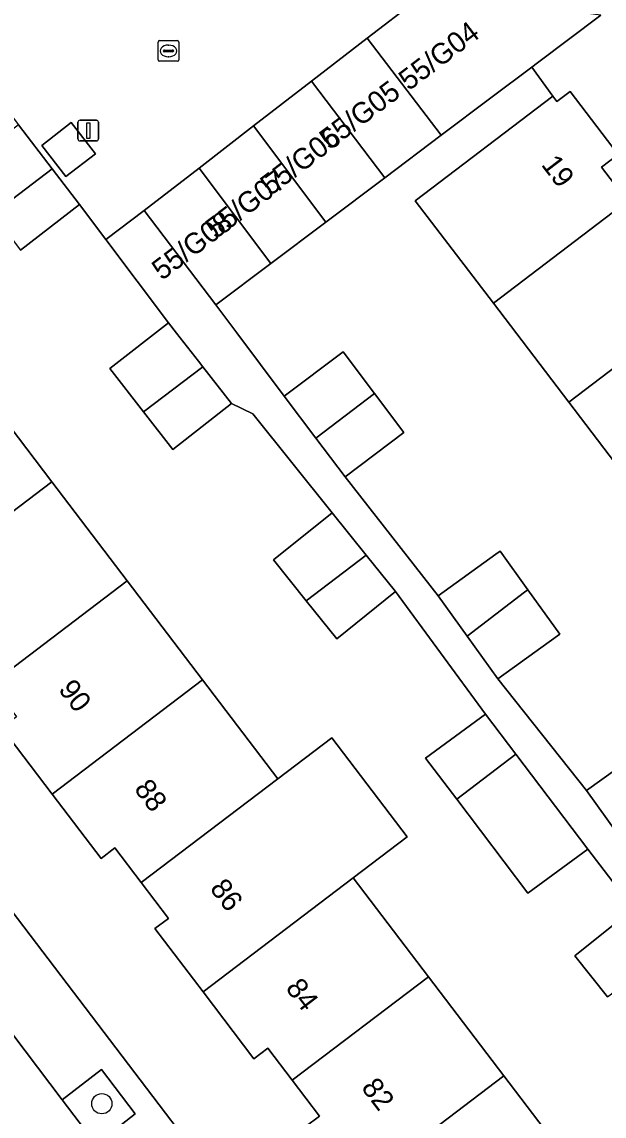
# Model space of a CAD drawing. Extents: x 160030 to 160839, y 385325 to 386450.
# Drawn here: x 160374.7 to 160402.8, y 385654.3 to 385707.1 of the extents above; entities that cross this region are included whole.
import ezdxf

# ---------------------------------------------------------------- set-up
doc = ezdxf.new("R2010")
doc.units = 0
for name, color, linetype in [('IMGEO_Berm_groen', 7, 'Continuous'), ('IMGEO_Boom', 7, 'Continuous'), ('IMGEO_Erf', 7, 'Continuous'), ('IMGEO_Fietspad_gesloten', 7, 'Continuous'), ('IMGEO_Kolk', 7, 'Continuous'), ('IMGEO_Lichtmast', 7, 'Continuous'), ('IMGEO_Muur', 7, 'Continuous'), ('IMGEO_Pand', 7, 'Continuous'), ('IMGEO_Pand_nummerreeks', 7, 'Continuous'), ('IMGEO_Voetpad_open', 7, 'Continuous')]:
    doc.layers.add(name, color=color, linetype=linetype)

msp = doc.modelspace()

# ---------------------------------------------------------------- linework, layer by layer
at = {"layer": 'IMGEO_Berm_groen'}
msp.add_lwpolyline([(160378.552, 385656.522), (160376.655, 385655.061), (160378.29, 385652.906), (160380.176, 385654.395)], close=True, dxfattribs=at)
at = {"layer": 'IMGEO_Boom'}
msp.add_circle((160378.564, 385654.88), 0.489, dxfattribs=at)
at = {"layer": 'IMGEO_Erf'}
for points in [[(160339.544, 385709.767), (160401.163, 385628.731)], [(160402.624, 385707.372), (160399.573, 385705.078), (160399.299, 385704.872), (160400.308, 385703.476), (160400.507, 385703.214), (160401.15, 385703.703), (160403.466, 385700.66), (160402.665, 385700.05), (160403.917, 385698.405)], [(160404.717, 385683.933), (160401.083, 385688.708), (160397.448, 385693.481), (160393.681, 385698.43), (160400.308, 385703.476), (160399.299, 385704.872), (160397.319, 385703.383), (160394.926, 385701.583), (160392.208, 385699.539), (160389.361, 385697.398), (160386.709, 385695.404), (160384.056, 385693.409), (160385.069, 385692.057), (160387.362, 385688.996), (160390.2, 385691.139), (160391.722, 385689.123), (160393.136, 385687.25), (160390.298, 385685.107), (160394.781, 385679.375), (160397.569, 385681.378), (160397.77, 385681.523), (160399.107, 385679.662), (160400.647, 385677.518), (160400.541, 385677.442), (160397.657, 385675.37), (160401.938, 385669.984), (160404.776, 385672.024)], [(160402.952, 385660.033), (160401.368, 385662.005), (160404.205, 385664.283), (160402.007, 385667.157), (160399.117, 385665.04), (160395.68, 385669.572), (160394.181, 385671.549), (160397.071, 385673.666), (160392.729, 385679.578), (160389.892, 385677.3), (160388.42, 385679.133), (160386.836, 385681.105), (160389.673, 385683.383), (160385.841, 385688.154), (160384.817, 385688.644), (160381.985, 385686.435), (160380.575, 385688.242), (160378.948, 385690.329), (160381.78, 385692.538), (160378.755, 385696.565), (160377.494, 385698.243), (160374.645, 385696.051)], [(160372.518, 385689.652), (160376.151, 385684.877), (160379.784, 385680.102), (160383.417, 385675.327), (160387.05, 385670.552), (160389.651, 385672.531), (160393.284, 385667.756), (160390.683, 385665.777), (160394.316, 385661.002), (160397.949, 385656.227), (160401.582, 385651.452)], [(160388.374, 385653.761), (160389.06, 385654.283), (160387.75, 385656.007), (160386.576, 385657.553), (160385.902, 385657.041), (160383.447, 385660.272), (160381.127, 385663.326), (160381.777, 385663.819), (160380.467, 385665.544), (160379.199, 385667.213), (160378.527, 385666.703), (160376.166, 385669.811), (160373.74, 385673.004)]]:
    msp.add_lwpolyline(points, dxfattribs=at)
at = {"layer": 'IMGEO_Fietspad_gesloten'}
msp.add_lwpolyline([(160397.145, 385622.614), (160400.065, 385624.282), (160397.346, 385627.892), (160393.079, 385633.494), (160391.247, 385635.898), (160385.777, 385643.076), (160383.977, 385645.439), (160378.29, 385652.906), (160376.655, 385655.061), (160371.275, 385662.152), (160369.368, 385664.665), (160363.85, 385671.938), (160361.976, 385674.409), (160356.639, 385681.442), (160354.764, 385683.91), (160349.583, 385690.729), (160347.708, 385693.198), (160342.44, 385700.132), (160340.557, 385702.595), (160336.836, 385707.457)], dxfattribs=at)
at = {"layer": 'IMGEO_Kolk'}
for p, q in [((160381.277, 385705.226), (160381.277, 385706.078)), ((160381.352, 385706.152), (160382.204, 385706.152)), ((160381.765, 385705.932), (160381.79, 385705.932)), ((160382.278, 385706.078), (160382.278, 385705.226)), ((160381.536, 385705.646), (160381.536, 385705.658)), ((160381.974, 385705.609), (160381.576, 385705.609)), ((160381.579, 385705.695), (160381.977, 385705.695)), ((160381.788, 385705.372), (160381.763, 385705.372)), ((160382.02, 385705.658), (160382.02, 385705.646)), ((160382.204, 385705.152), (160381.352, 385705.152))]:
    msp.add_line(p, q, dxfattribs=at)
for points in [[(160381.277, 385705.226), (160381.277, 385706.078)], [(160381.352, 385706.152), (160382.204, 385706.152)], [(160382.278, 385706.078), (160382.278, 385705.226)], [(160382.204, 385705.152), (160381.352, 385705.152)]]:
    msp.add_lwpolyline(points, dxfattribs=at)
for centre, radius, start, end in [((160381.354, 385706.076), 0.0765, 91.552, 178.448), ((160381.354, 385706.076), 0.0765, 91.552, 178.448), ((160382.202, 385706.076), 0.0765, 1.552, 88.448), ((160382.202, 385706.076), 0.0765, 1.552, 88.448), ((160381.576, 385705.655), 0.0403, 85.8775, 175.7526), ((160381.573, 385705.645), 0.0366, 178.938, 274.7102), ((160381.977, 385705.652), 0.043, 264.8664, 352.4533), ((160381.981, 385705.657), 0.0386, 1.7309, 96.639), ((160381.354, 385705.228), 0.0765, 181.552, 268.448), ((160381.354, 385705.228), 0.0765, 181.552, 268.448), ((160382.202, 385705.228), 0.0765, 271.552, 358.448), ((160382.202, 385705.228), 0.0765, 271.552, 358.448)]:
    msp.add_arc(centre, radius, start, end, dxfattribs=at)
for centre, major_axis, ratio, start_param, end_param in [((160381.764, 385705.652), (-0.387, 0.002), 0.722429, 4.712389, 7.853982), ((160381.789, 385705.652), (-0.39, 0.002), 0.717154, 1.570796, 4.712389)]:
    msp.add_ellipse(centre, major_axis=major_axis, ratio=ratio, start_param=start_param, end_param=end_param, dxfattribs=at)
at = {"layer": 'IMGEO_Lichtmast'}
for p, q in [((160377.413, 385701.41), (160377.413, 385702.21)), ((160377.413, 385702.21), (160377.413, 385701.41)), ((160377.513, 385702.31), (160378.303, 385702.31)), ((160378.303, 385702.31), (160377.513, 385702.31)), ((160378.403, 385702.21), (160378.403, 385701.41)), ((160378.403, 385701.41), (160378.403, 385702.21)), ((160378.303, 385701.31), (160377.513, 385701.31)), ((160377.513, 385701.31), (160378.303, 385701.31))]:
    msp.add_line(p, q, dxfattribs=at)
msp.add_lwpolyline([(160377.833, 385702.185), (160377.983, 385702.185), (160377.983, 385701.435), (160377.833, 385701.435), (160377.833, 385702.185)], dxfattribs=at)
for centre, start, end in [((160377.513, 385702.21), 90, 180), ((160377.513, 385702.21), 90, 180), ((160378.303, 385702.21), 0, 90), ((160378.303, 385702.21), 360, 90), ((160377.513, 385701.41), 180, 270), ((160377.513, 385701.41), 180, 270), ((160378.303, 385701.41), 270, 0), ((160378.303, 385701.41), 270, 0)]:
    msp.add_arc(centre, 0.1, start, end, dxfattribs=at)
at = {"layer": 'IMGEO_Muur'}
msp.add_lwpolyline([(160377.494, 385698.243), (160378.755, 385696.565), (160381.78, 385692.538)], dxfattribs=at)
at = {"layer": 'IMGEO_Pand'}
for points in [[(160402.624, 385707.372), (160394.209, 385708.475), (160393.754, 385708.123), (160391.362, 385706.273), (160394.926, 385701.583), (160397.319, 385703.383), (160399.299, 385704.872), (160399.573, 385705.078)], [(160388.672, 385704.193), (160392.208, 385699.539), (160394.926, 385701.583), (160391.362, 385706.273)], [(160385.877, 385702.032), (160389.361, 385697.398), (160392.208, 385699.539), (160388.672, 385704.193)], [(160403.917, 385698.405), (160402.665, 385700.05), (160403.466, 385700.66), (160401.15, 385703.703), (160400.507, 385703.214), (160400.308, 385703.476), (160393.681, 385698.43), (160397.448, 385693.481)], [(160374.539, 385702.084), (160371.69, 385699.893), (160373.306, 385697.791), (160376.167, 385699.968)], [(160378.253, 385700.696), (160377.086, 385702.197), (160375.663, 385701.09), (160376.83, 385699.589)], [(160383.251, 385700.001), (160386.709, 385695.404), (160389.361, 385697.398), (160385.877, 385702.032)], [(160376.167, 385699.968), (160373.306, 385697.791), (160374.645, 385696.051), (160377.494, 385698.243)], [(160380.603, 385697.953), (160384.056, 385693.409), (160386.709, 385695.404), (160383.251, 385700.001)], [(160397.448, 385693.481), (160401.083, 385688.708), (160408.339, 385694.231), (160405.868, 385697.477), (160405.08, 385696.877), (160403.917, 385698.405)], [(160401.083, 385688.708), (160404.717, 385683.933), (160411.21, 385688.876), (160409.935, 385690.551), (160410.698, 385691.132), (160408.339, 385694.231)], [(160381.78, 385692.538), (160378.948, 385690.329), (160380.575, 385688.242), (160383.434, 385690.417), (160383.221, 385690.69), (160382.166, 385692.043)], [(160391.722, 385689.123), (160390.2, 385691.139), (160387.362, 385688.996), (160388.892, 385686.969)], [(160380.575, 385688.242), (160381.985, 385686.435), (160384.817, 385688.644), (160383.434, 385690.417)], [(160365.955, 385684.66), (160367.154, 385683.082), (160366.459, 385682.554), (160368.89, 385679.354), (160376.151, 385684.877), (160372.518, 385689.652)], [(160388.892, 385686.969), (160390.298, 385685.107), (160393.136, 385687.25), (160391.722, 385689.123)], [(160379.784, 385680.102), (160376.151, 385684.877), (160368.89, 385679.354), (160371.243, 385676.257), (160371.962, 385676.804), (160373.239, 385675.123)], [(160389.673, 385683.383), (160386.836, 385681.105), (160388.42, 385679.133), (160391.317, 385681.336)], [(160389.892, 385677.3), (160392.729, 385679.578), (160391.317, 385681.336), (160388.42, 385679.133)], [(160398.953, 385679.545), (160399.107, 385679.662), (160397.77, 385681.523), (160397.569, 385681.378), (160394.781, 385679.375), (160396.177, 385677.431)], [(160383.417, 385675.327), (160379.784, 385680.102), (160373.239, 385675.123), (160374.443, 385673.538), (160373.74, 385673.004), (160376.166, 385669.811)], [(160396.177, 385677.431), (160397.657, 385675.37), (160400.541, 385677.442), (160400.647, 385677.518), (160399.107, 385679.662), (160398.953, 385679.545)], [(160376.166, 385669.811), (160378.527, 385666.703), (160379.199, 385667.213), (160380.467, 385665.544), (160387.05, 385670.552), (160383.417, 385675.327)], [(160398.528, 385671.744), (160397.071, 385673.666), (160394.181, 385671.549), (160395.68, 385669.572)], [(160390.683, 385665.777), (160393.284, 385667.756), (160389.651, 385672.531), (160387.05, 385670.552), (160380.467, 385665.544), (160381.777, 385663.819), (160381.127, 385663.326), (160383.447, 385660.272)], [(160398.528, 385671.744), (160395.68, 385669.572), (160399.117, 385665.04), (160402.007, 385667.157)], [(160406.227, 385670.003), (160404.776, 385672.024), (160401.938, 385669.984), (160403.445, 385667.886)], [(160394.316, 385661.002), (160390.683, 385665.777), (160383.447, 385660.272), (160385.902, 385657.041), (160386.576, 385657.553), (160387.75, 385656.007)], [(160404.205, 385664.283), (160401.368, 385662.005), (160402.952, 385660.033), (160405.849, 385662.236)], [(160387.75, 385656.007), (160389.06, 385654.283), (160388.374, 385653.761), (160390.694, 385650.708), (160397.949, 385656.227), (160394.316, 385661.002)], [(160390.694, 385650.708), (160393.149, 385647.476), (160393.774, 385647.952), (160394.949, 385646.406), (160401.582, 385651.452), (160397.949, 385656.227)]]:
    msp.add_lwpolyline(points, close=True, dxfattribs=at)
at = {"layer": 'IMGEO_Voetpad_open'}
for points in [[(160401.163, 385628.731), (160339.544, 385709.767)], [(160370.244, 385707.726), (160374.539, 385702.084), (160376.167, 385699.968), (160377.494, 385698.243), (160378.755, 385696.565), (160380.603, 385697.953), (160383.251, 385700.001), (160385.877, 385702.032), (160388.672, 385704.193), (160391.362, 385706.273), (160393.754, 385708.123)], [(160403.445, 385667.886), (160401.938, 385669.984), (160397.657, 385675.37), (160396.177, 385677.431), (160394.781, 385679.375), (160390.298, 385685.107), (160388.892, 385686.969), (160387.362, 385688.996), (160385.069, 385692.057), (160384.056, 385693.409), (160380.603, 385697.953), (160378.755, 385696.565), (160381.78, 385692.538), (160382.166, 385692.043), (160383.221, 385690.69), (160383.434, 385690.417), (160384.817, 385688.644), (160385.841, 385688.154), (160389.673, 385683.383), (160391.317, 385681.336), (160392.729, 385679.578), (160397.071, 385673.666), (160398.528, 385671.744), (160402.007, 385667.157), (160404.205, 385664.283)], [(160371.275, 385662.152), (160376.655, 385655.061), (160378.552, 385656.522), (160380.176, 385654.395), (160378.29, 385652.906), (160383.977, 385645.439), (160385.913, 385647.022), (160387.785, 385644.61), (160385.777, 385643.076), (160391.247, 385635.898), (160393.117, 385637.342), (160394.955, 385634.94), (160393.079, 385633.494), (160397.346, 385627.892)]]:
    msp.add_lwpolyline(points, dxfattribs=at)
msp.add_lwpolyline([(160378.253, 385700.696), (160376.83, 385699.589), (160375.663, 385701.09), (160377.086, 385702.197)], close=True, dxfattribs=at)

# ---------------------------------------------------------------- texts
at = {"layer": 'IMGEO_Pand_nummerreeks'}
for s, rotation, p in [('55/G04', 37.1735, (160393.369, 385703.703)), ('55/G05', 37.1752, (160389.545, 385700.85)), ('55/G06', 37.1752, (160386.694, 385698.637)), ('19', 307.254, (160399.724, 385700.16)), ('55/G07', 37.1752, (160384.056, 385696.553)), ('55/G08', 37.1752, (160381.463, 385694.555)), ('90', 307.2538, (160376.434, 385674.853)), ('88', 307.2538, (160380.087, 385670.049)), ('86', 307.2535, (160383.74, 385665.247)), ('84', 307.2538, (160387.392, 385660.444)), ('82', 307.2538, (160391.043, 385655.643))]:
    msp.add_text(s, height=1, rotation=rotation, dxfattribs=at).set_placement(p)

doc.saveas('drawing.dxf')
